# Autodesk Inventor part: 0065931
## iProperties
Created: 2005-06
Part Number: 0065931
Material: Stahl
Document SubType Name: Modeling
Designer: Armin Walder
Cost Center: 0,03 kg
Authority: 3837,219 mm^3
SaveDate: 2006-09-28
SaveTime: 09:26
FileName: 0065931
TotalMass: 0,03 kg
TotalVolume: 3837,219 mm^3
Author: Armin Walder
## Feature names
1. Drehung1 [Revolution]
2. Fase1 [Chamfer]
3. Fase2 [Chamfer]
4. Bohrung1 [Hole]
5. Extrusion1
6. Runde Anordnung1 [Circular Pattern]
7. Bohrung3 [Hole]
8. Fase3 [Chamfer]
9. Bohrung4 [Hole]
